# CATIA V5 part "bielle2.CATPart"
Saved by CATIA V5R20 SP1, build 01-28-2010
Part number: Part1.1.2
Bounding box of the stored display mesh (mm): x 43 to 87, y 0 to 5, z 28.093 to 41.907
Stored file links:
  E:\EDELI\gcausse\Edeli_2012_686_gcausse\bielle2.CATPart
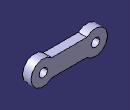
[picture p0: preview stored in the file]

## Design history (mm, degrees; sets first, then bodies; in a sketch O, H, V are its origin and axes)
Parameters
  long = 0.03
  diamtrou = 0.005
Body1 (main body)
  Sketch1 on zx-plane, origin (0, 0, 0), H (-1, 0, 0), V (0, 0, 1)
    line L1 (-54.899, 40) -> (-75.101, 40)
    line L2 (-54.899, 30) -> (-75.101, 30)
    arc A1 centre (-50, 35) radius 7 from (-54.899, 40) to (-54.899, 30) cw
    point P5 (-50, 35)
    point P6 (-45.101, 30)
    arc A2 centre (-80, 35) radius 7 from (-75.101, 40) to (-75.101, 30) ccw
    point P7 (-80, 35)
    circle A3 centre (-50, 35) radius 2.5
    distance P7 L1 = 5
    distance P5 L2 = 5
    distance L2 L1 = 10
    radius A1 = 7
    radius A2 = 7
    distance P5 P7 = 30 {= long}
    radius A3 = 2.5
    horizontal: L1 H, L2 H
    coincidence: A1 P6, P6 L2
  Pad1: profile Sketch1, direction (0, 1, 0), length 5
  Sketch2 on end face of Pad1, origin (0, 5, 0), H (-1, 0, 0), V (0, 0, 1)
    circle A1 centre (-80, 35) radius 2.5
    reference projected arc E1 centre (-80, 35) radius 7 from (-75.101, 40) to (-75.101, 30) ccw from edge [face of Pad1 from Sketch1.A2 | end face of Pad1]
    reference projected arc E2 centre (-80, 35) radius 7 from (-75.101, 40) to (-75.101, 30) ccw from edge [face of Pad1 from Sketch1.A2 | end face of Pad1]
    radius A1 = 2.5
    radius E2 = 7 (reference)
    concentricity: A1 E1
  Pocket1: profile Sketch2, direction (0, -1, 0), length 5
